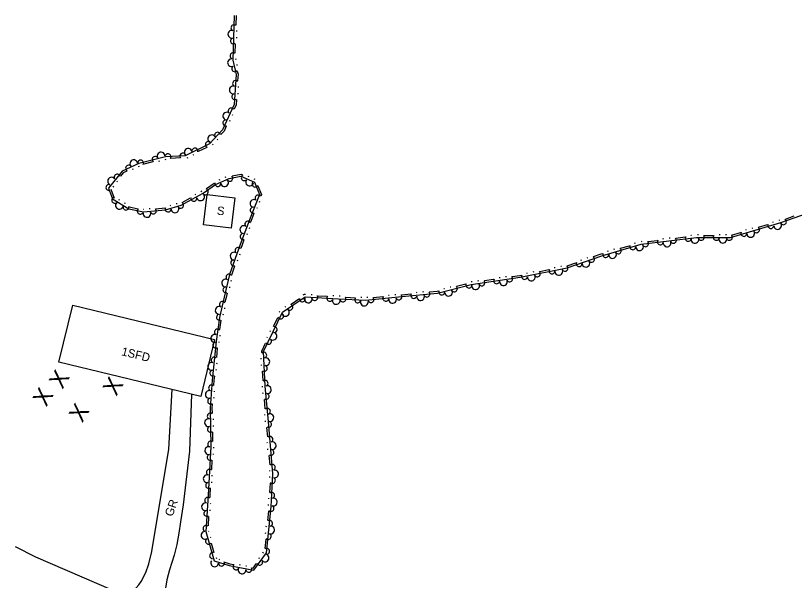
# Model space of a CAD drawing. Extents: x 2030130 to 2036320, y 723205 to 762423.
# Drawn here: x 2032703.1 to 2033043.9, y 760651.9 to 760899.1 of the extents above; entities that cross this region are included whole.
import ezdxf

# ---------------------------------------------------------------- set-up
doc = ezdxf.new("R2010")
doc.units = 0
for name, color, linetype in [('Draft_Station Labels Major', 7, 'Continuous'), ('Draft_Station Tics Major', 7, 'Continuous'), ('Exist Terrain Model Ground Surface', 7, 'Continuous'), ('Old_Level_23', 7, 'Continuous'), ('Old_Level_28', 7, 'Continuous')]:
    doc.layers.add(name, color=color, linetype=linetype)

msp = doc.modelspace()

# ---------------------------------------------------------------- linework, layer by layer
at = {"layer": 'Draft_Station Labels Major'}
for points in [[(2032752.34, 760644.62), (2032757.03, 760649.97), (2032757.96, 760651.43), (2032760.11, 760655.38), (2032761.37, 760659.07), (2032762.73, 760664.47), (2032770.18, 760709.31), (2032771.53, 760735.41)], [(2032780.04, 760733.35), (2032779.16, 760708.37), (2032776.48, 760684.96), (2032775.31, 760677.51), (2032774.46, 760672.51), (2032773.6, 760667.55), (2032772.54, 760662.87), (2032770.43, 760656.46), (2032769.22, 760652.17), (2032768.74, 760648.45), (2032768.83, 760645.51), (2032768.92, 760637.43)], [(2032711.99, 760662.1), (2032703.07, 760666.56)], [(2032832.59, 760613.36), (2032771.69, 760636.24), (2032711.99, 760662.1)]]:
    msp.add_lwpolyline(points, dxfattribs=at)
at = {"layer": 'Draft_Station Tics Major'}
for points in [[(2032798.8, 760899.06), (2032798.14, 760879.49), (2032799.59, 760873.3), (2032798.75, 760860.19), (2032793.65, 760849), (2032787.97, 760842.9), (2032777.3, 760837.65), (2032768.66, 760837.26), (2032756.95, 760834.28), (2032749.65, 760830.97), (2032743.72, 760823.56), (2032745.5, 760818.8), (2032752.65, 760814.53), (2032758.98, 760813.13), (2032768.63, 760814.05), (2032775.55, 760816.12), (2032785.15, 760821.28), (2032790.56, 760825.06), (2032796.57, 760827.79), (2032801.66, 760828.77), (2032807.58, 760826.18), (2032809.76, 760820.77), (2032805.72, 760810.4), (2032801.39, 760798.94), (2032796.75, 760785.79), (2032794.4, 760775.89), (2032792.27, 760766.86), (2032790.83, 760756.37), (2032789.08, 760739.57), (2032788.21, 760727.24), (2032788.5, 760710.53), (2032787.32, 760689.21), (2032786.31, 760673.29), (2032789.94, 760660.49), (2032796.57, 760658.39), (2032807.39, 760656.32), (2032812.88, 760663.96), (2032814.92, 760684.01), (2032815.62, 760698.69), (2032813.7, 760721.21), (2032812.31, 760736.89), (2032811.61, 760752.06), (2032819.84, 760769.24), (2032829.81, 760775.92), (2032844.36, 760775.15), (2032856.14, 760774.47), (2032872.12, 760776.08), (2032887.67, 760777.61), (2032902.42, 760781.36), (2032923.89, 760784.53), (2032944.5, 760788.67), (2032959.57, 760793.98), (2032976.86, 760798.98), (2033001.04, 760802.01), (2033015.88, 760802.01), (2033037.97, 760808.43), (2033060.92, 760816.48)], [(2032799.62, 760899.03), (2032799.48, 760894.93)], [(2032799.81, 760892.46), (2032799.79, 760892.05)], [(2032799.71, 760889.59), (2032799.7, 760889.18)], [(2032799.2, 760886.73), (2032799.07, 760882.64)], [(2032799.4, 760880.16), (2032799.38, 760879.75)], [(2032799.83, 760877.67), (2032799.92, 760877.27)], [(2032800.08, 760874.78), (2032800.41, 760873.37), (2032800.23, 760870.48)], [(2032800.3, 760865.13), (2032800.27, 760864.73)], [(2032800.48, 760868), (2032800.46, 760867.59)], [(2032799.71, 760862.3), (2032799.56, 760859.99), (2032798.69, 760858.09)], [(2032798.05, 760855.68), (2032797.88, 760855.3)], [(2032796.86, 760853.07), (2032796.69, 760852.69)], [(2032795.29, 760850.62), (2032794.34, 760848.54), (2032792.93, 760847.02)], [(2032791.55, 760844.94), (2032791.27, 760844.64)], [(2032786.71, 760841.36), (2032783.03, 760839.55)], [(2032789.59, 760842.83), (2032789.31, 760842.53)], [(2032781, 760838.1), (2032780.64, 760837.92)], [(2032763.17, 760835.02), (2032759.19, 760834)], [(2032766.05, 760835.33), (2032765.65, 760835.23)], [(2032768.83, 760836.04), (2032768.44, 760835.94)], [(2032775.12, 760836.73), (2032771.02, 760836.55)], [(2032778.42, 760836.83), (2032778.05, 760836.65)], [(2032751.73, 760831.02), (2032750.17, 760830.31), (2032748.93, 760828.76)], [(2032754.52, 760831.83), (2032754.15, 760831.66)], [(2032757.13, 760833.01), (2032756.76, 760832.84)], [(2032794.81, 760828.34), (2032795.18, 760828.51)], [(2032797.88, 760828.88), (2032801.75, 760829.62), (2032802.37, 760829.35)], [(2032804.78, 760828.74), (2032805.16, 760828.58)], [(2032807.41, 760827.59), (2032807.79, 760827.43)], [(2032745.91, 760824.34), (2032745.66, 760824.02)], [(2032747.71, 760826.58), (2032747.45, 760826.26)], [(2032786.64, 760823.32), (2032790, 760825.67)], [(2032792.19, 760827.15), (2032792.57, 760827.32)], [(2032809.14, 760824.49), (2032810.64, 760820.78), (2032810.37, 760820.08)], [(2032744.8, 760823.02), (2032746.24, 760819.18)], [(2032781.62, 760820.78), (2032781.98, 760820.97)], [(2032784.15, 760822.13), (2032784.51, 760822.33)], [(2032748.17, 760818.64), (2032748.52, 760818.43)], [(2032776.03, 760817.31), (2032779.65, 760819.25)], [(2032809.86, 760817.63), (2032809.71, 760817.25)], [(2032750.63, 760817.17), (2032750.98, 760816.96)], [(2032752.89, 760815.34), (2032752.96, 760815.3), (2032756.62, 760814.49)], [(2032759.05, 760814.37), (2032759.13, 760814.38)], [(2032761.58, 760814.61), (2032761.99, 760814.65)], [(2032764.48, 760814.47), (2032768.48, 760814.86)], [(2032770.65, 760815.93), (2032771.04, 760816.05)], [(2032773.39, 760816.75), (2032773.79, 760816.87)], [(2032808.82, 760814.96), (2032808.67, 760814.58)], [(2032807.39, 760812.43), (2032806.49, 760810.11), (2032805.92, 760808.62)], [(2033039.98, 760810), (2033043.85, 760811.36)], [(2033028.25, 760806.46), (2033032.18, 760807.6)], [(2033034.43, 760808.69), (2033034.83, 760808.8)], [(2033037.19, 760809.48), (2033037.58, 760809.6)], [(2032805.44, 760806.17), (2032805.29, 760805.79)], [(2033016.43, 760803.03), (2033020.37, 760804.17)], [(2033022.62, 760805.25), (2033023.01, 760805.37)], [(2033025.38, 760806.05), (2033025.77, 760806.17)], [(2032803.02, 760800.94), (2032802.16, 760798.66), (2032801.61, 760797.11)], [(2032804.42, 760803.48), (2032804.27, 760803.1)], [(2032976.95, 760800.23), (2032977.35, 760800.28)], [(2032979.85, 760800.18), (2032983.92, 760800.69)], [(2032986.3, 760801.4), (2032986.71, 760801.45)], [(2032989.16, 760801.76), (2032989.56, 760801.81)], [(2032992.05, 760801.71), (2032996.12, 760802.22)], [(2032998.51, 760802.93), (2032998.92, 760802.98)], [(2033001.52, 760803.24), (2033001.93, 760803.24)], [(2033004.39, 760802.83), (2033008.49, 760802.83)], [(2033010.95, 760803.24), (2033011.36, 760803.24)], [(2033013.82, 760803.24), (2033014.23, 760803.24)], [(2032964.93, 760796.81), (2032965.33, 760796.93)], [(2032967.8, 760797.21), (2032971.74, 760798.35)], [(2032973.99, 760799.43), (2032974.39, 760799.54)], [(2032801.18, 760794.66), (2032801.04, 760794.27)], [(2032956, 760793.59), (2032959.32, 760794.76), (2032959.92, 760794.94)], [(2032962.17, 760796.01), (2032962.57, 760796.13)], [(2032800.22, 760791.95), (2032800.09, 760791.56)], [(2032944.4, 760789.5), (2032948.27, 760790.87)], [(2032950.45, 760792.07), (2032950.83, 760792.21)], [(2032953.16, 760793.02), (2032953.54, 760793.16)], [(2032798.88, 760789.38), (2032797.52, 760785.51)], [(2032929.56, 760786.92), (2032929.96, 760787)], [(2032932.45, 760787.09), (2032936.47, 760787.89)], [(2032938.81, 760788.78), (2032939.21, 760788.86)], [(2032941.62, 760789.34), (2032942.02, 760789.43)], [(2032908.23, 760783.05), (2032912.29, 760783.65)], [(2032914.66, 760784.41), (2032915.07, 760784.47)], [(2032917.5, 760784.83), (2032917.91, 760784.89)], [(2032920.4, 760784.84), (2032923.75, 760785.34), (2032924.41, 760785.47)], [(2032926.74, 760786.36), (2032927.14, 760786.44)], [(2032796.72, 760780.31), (2032796.62, 760779.91)], [(2032797.38, 760783.1), (2032797.28, 760782.71)], [(2032893.22, 760780.29), (2032893.62, 760780.39)], [(2032896.1, 760780.6), (2032900.08, 760781.61)], [(2032902.49, 760782.61), (2032902.9, 760782.67)], [(2032905.33, 760783.03), (2032905.74, 760783.09)], [(2032795.65, 760777.61), (2032795.2, 760775.7), (2032794.71, 760773.62)], [(2032828.89, 760776.78), (2032829.47, 760777.17), (2032830, 760777.14)], [(2032832.45, 760777.01), (2032832.86, 760776.99)], [(2032835.3, 760776.45), (2032839.39, 760776.23)], [(2032841.87, 760776.51), (2032842.28, 760776.49)], [(2032844.75, 760776.36), (2032845.15, 760776.34)], [(2032866.22, 760776.72), (2032866.62, 760776.76)], [(2032869.07, 760777.01), (2032869.48, 760777.05)], [(2032871.97, 760776.89), (2032872.04, 760776.9), (2032876.05, 760777.29)], [(2032878.46, 760777.94), (2032878.87, 760777.98)], [(2032881.32, 760778.22), (2032881.73, 760778.26)], [(2032884.22, 760778.09), (2032887.53, 760778.42), (2032888.16, 760778.58)], [(2032890.44, 760779.58), (2032890.84, 760779.68)], [(2032823.66, 760772.79), (2032827.07, 760775.07)], [(2032847.59, 760775.78), (2032851.68, 760775.55)], [(2032854.16, 760775.81), (2032854.57, 760775.79)], [(2032856.83, 760775.77), (2032857.24, 760775.82)], [(2032859.73, 760775.65), (2032863.81, 760776.07)], [(2032794.54, 760771.13), (2032794.45, 760770.73)], [(2032818.48, 760769.24), (2032818.65, 760769.61)], [(2032821.05, 760771.53), (2032821.39, 760771.76)], [(2032793.88, 760768.34), (2032793.79, 760767.94)], [(2032816.01, 760763.14), (2032817.78, 760766.84)], [(2032792.94, 760765.7), (2032792.38, 760761.64)], [(2032814.4, 760760.73), (2032814.58, 760761.1)], [(2032792.06, 760756.29), (2032792.05, 760756.22), (2032792.02, 760755.93)], [(2032792.45, 760759.14), (2032792.4, 760758.74)], [(2032813.16, 760758.14), (2032813.34, 760758.51)], [(2032791.36, 760753.52), (2032790.93, 760749.45)], [(2032810.81, 760751.62), (2032810.78, 760752.23), (2032812.47, 760755.75)], [(2032810.53, 760748.73), (2032810.51, 760749.14)], [(2032791.09, 760746.96), (2032791.04, 760746.55)], [(2032810.66, 760745.86), (2032810.64, 760746.27)], [(2032790.79, 760744.1), (2032790.75, 760743.69)], [(2032811.37, 760739.33), (2032811.19, 760743.42)], [(2032790.08, 760741.29), (2032789.9, 760739.5), (2032789.74, 760737.23)], [(2032811.12, 760736.39), (2032811.08, 760736.8), (2032811.08, 760736.82)], [(2032789.97, 760734.75), (2032789.94, 760734.34)], [(2032811.37, 760733.53), (2032811.34, 760733.94)], [(2032789.16, 760729.05), (2032789.03, 760727.22), (2032789.07, 760725.02)], [(2032789.77, 760731.88), (2032789.74, 760731.47)], [(2032812.36, 760727.03), (2032812, 760731.11)], [(2032789.52, 760722.57), (2032789.53, 760722.16)], [(2032812.21, 760724.13), (2032812.17, 760724.54)], [(2032789.57, 760719.7), (2032789.58, 760719.29)], [(2032812.46, 760721.27), (2032812.43, 760721.68)], [(2032813.43, 760714.77), (2032813.08, 760718.86)], [(2032789.21, 760716.82), (2032789.28, 760712.72)], [(2032813.26, 760711.88), (2032813.23, 760712.29)], [(2032789.71, 760710.18), (2032789.69, 760709.77)], [(2032813.51, 760709.02), (2032813.47, 760709.43)], [(2032789.55, 760707.32), (2032789.53, 760706.91)], [(2032814.47, 760702.52), (2032814.12, 760706.6)], [(2032788.98, 760704.47), (2032788.76, 760700.38)], [(2032814.31, 760699.62), (2032814.27, 760700.03)], [(2032788.87, 760695.03), (2032788.85, 760694.62)], [(2032789.03, 760697.9), (2032789.01, 760697.49)], [(2032814.3, 760696.92), (2032814.32, 760697.33)], [(2032788.3, 760692.19), (2032788.14, 760689.16), (2032788.07, 760688.09)], [(2032814.4, 760690.34), (2032814.6, 760694.44)], [(2032813.86, 760687.5), (2032813.87, 760687.9)], [(2032788.32, 760685.6), (2032788.3, 760685.19)], [(2032813.72, 760684.63), (2032813.74, 760685.04)], [(2032788.14, 760682.74), (2032788.12, 760682.33)], [(2032813.5, 760678.12), (2032813.91, 760682.2)], [(2032787.55, 760679.9), (2032787.29, 760675.81)], [(2032812.8, 760675.31), (2032812.84, 760675.72)], [(2032787.55, 760673.43), (2032787.58, 760673.34)], [(2032788.25, 760670.97), (2032788.36, 760670.58)], [(2032812.51, 760672.45), (2032812.55, 760672.86)], [(2032788.64, 760668.1), (2032789.76, 760664.15)], [(2032812.25, 760665.88), (2032812.67, 760669.96)], [(2032811.29, 760663.85), (2032811.53, 760664.18)], [(2032790.82, 760661.9), (2032790.93, 760661.5)], [(2032791.99, 760661.13), (2032792.38, 760661.01)], [(2032809.61, 760661.52), (2032809.85, 760661.85)], [(2032794.6, 760659.88), (2032796.77, 760659.19), (2032798.47, 760658.86)], [(2032800.97, 760658.8), (2032801.37, 760658.72)], [(2032803.78, 760658.26), (2032804.19, 760658.18)], [(2032806.53, 760657.32), (2032807.03, 760657.22), (2032808.51, 760659.28)]]:
    msp.add_lwpolyline(points, dxfattribs=at)
for centre, radius, start, end in [((2032797.7, 760890.89), 1.69, 74.0505, 282.123), ((2032798.62, 760893.73), 1.3, 48.8553, 249.6518), ((2032798.43, 760887.99), 1.3, 106.5217, 307.3183), ((2032798.21, 760881.43), 1.3, 48.8553, 249.6518), ((2032797.55, 760878.4), 1.69, 89.1091, 297.1815), ((2032799.01, 760875.79), 1.3, 121.5802, 322.3768), ((2032799.33, 760869.31), 1.3, 47.1163, 247.9128), ((2032798.33, 760866.49), 1.69, 72.3115, 280.384), ((2032798.97, 760863.58), 1.3, 104.7827, 305.5793), ((2032797.44, 760857.31), 1.3, 26.2603, 227.0569), ((2032795.5, 760855.03), 1.69, 51.4556, 259.5281), ((2032795.06, 760852.08), 1.3, 83.9268, 284.7233), ((2032791.49, 760846.68), 1.3, 7.8371, 208.6336), ((2032788.93, 760845.13), 1.69, 33.0323, 241.1048), ((2032787.45, 760842.64), 1.3, 44.5989, 245.3955), ((2032766.74, 760837.62), 1.69, 0.2623, 208.3347), ((2032769.75, 760837.31), 1.3, 323.3511, 164.1476), ((2032776.31, 760837.61), 1.3, 21.0175, 221.8141), ((2032778.62, 760839.22), 1.69, 12.1277, 220.2002), ((2032781.56, 760839.75), 1.3, 346.9324, 187.729), ((2032754.79, 760834.2), 1.69, 10.3078, 218.3803), ((2032757.8, 760834.5), 1.3, 335.067, 175.8636), ((2032764.16, 760836.12), 1.3, 32.7335, 233.53), ((2032752.52, 760832.27), 1.3, 42.779, 243.5755), ((2032745.08, 760826.58), 1.69, 37.307, 245.3795), ((2032747.52, 760828.31), 1.3, 12.1118, 212.9083), ((2032796.83, 760827.84), 1.3, 209.3174, 50.114), ((2032803.16, 760828.11), 1.3, 117.1354, 317.9319), ((2032743.93, 760823.83), 1.3, 69.7782, 270.5748), ((2032791.58, 760825.52), 1.3, 165.223, 6.0196), ((2032794.54, 760825.96), 1.69, 190.4183, 38.4908), ((2032805.47, 760826.21), 1.69, 142.3306, 350.4031), ((2032807.92, 760825.32), 1.3, 130.4399, 331.2364), ((2032784.04, 760819.74), 1.69, 194.2099, 42.2824), ((2032786.1, 760821.94), 1.3, 233.3966, 74.1932), ((2032746.48, 760818.22), 1.3, 109.8851, 310.6816), ((2032748.52, 760816.04), 1.69, 135.0804, 343.1528), ((2032781.12, 760819.11), 1.3, 169.0146, 9.8112), ((2032807.35, 760816.85), 1.69, 54.68, 262.7525), ((2032809.16, 760819.23), 1.3, 29.4847, 230.2813), ((2032751.41, 760815.27), 1.3, 167.5515, 8.3481), ((2032757.64, 760813.42), 1.3, 128.2515, 329.048), ((2032763.33, 760813.54), 1.3, 203.8875, 44.684), ((2032769.82, 760814.4), 1.3, 157.4154, 358.212), ((2032772.8, 760814.44), 1.69, 182.6107, 30.6831), ((2032775.32, 760816.05), 1.3, 215.0819, 55.8784), ((2032807.08, 760813.88), 1.3, 87.1512, 287.9478), ((2032760.55, 760812.45), 1.69, 171.4163, 19.4888), ((2032802.94, 760805.36), 1.69, 55.2371, 263.3096), ((2032804.72, 760807.76), 1.3, 30.0419, 230.8384), ((2033033.59, 760807.16), 1.3, 156.9706, 357.7672), ((2033036.58, 760807.17), 1.69, 182.1659, 30.2384), ((2033039.09, 760808.82), 1.3, 217.7548, 58.5514), ((2032802.69, 760802.39), 1.3, 87.7083, 288.5049), ((2033021.78, 760803.73), 1.3, 156.9706, 357.7672), ((2033024.77, 760803.74), 1.69, 182.1659, 30.2384), ((2033027.29, 760805.33), 1.3, 214.6371, 55.4336), ((2032985.24, 760800.03), 1.3, 147.9155, 348.7121), ((2032988.19, 760799.57), 1.69, 173.1108, 21.1833), ((2032990.94, 760800.74), 1.3, 205.582, 46.3785), ((2032997.45, 760801.56), 1.3, 147.9155, 348.7121), ((2033000.4, 760801.1), 1.69, 173.1108, 21.1833), ((2033003.16, 760802.01), 1.3, 198.4444, 39.241), ((2033009.72, 760802.01), 1.3, 140.778, 341.5746), ((2033012.59, 760801.19), 1.69, 165.9733, 14.0457), ((2033015.46, 760802.01), 1.3, 198.4444, 39.241), ((2032800.43, 760796.23), 1.3, 31.3535, 232.1501), ((2032966.85, 760796.09), 1.3, 214.5511, 55.3477), ((2032973.15, 760797.91), 1.3, 156.8846, 357.6812), ((2032976.14, 760797.92), 1.69, 182.0799, 30.1524), ((2032978.73, 760799.21), 1.3, 205.582, 46.3785), ((2032798.7, 760793.79), 1.69, 56.5488, 264.6212), ((2032955.11, 760792.41), 1.3, 217.8582, 58.6548), ((2032961.33, 760794.49), 1.3, 156.8846, 357.6812), ((2032964.32, 760794.5), 1.69, 182.0799, 30.1524), ((2032798.52, 760790.81), 1.3, 89.02, 289.8165), ((2032949.7, 760790.5), 1.3, 160.1917, 0.9883), ((2032952.68, 760790.68), 1.69, 185.387, 33.4595), ((2032931.41, 760786.04), 1.3, 209.7901, 50.5866), ((2032937.84, 760787.33), 1.3, 152.1236, 352.9202), ((2032940.82, 760787.09), 1.69, 177.3189, 25.3913), ((2032943.47, 760788.46), 1.3, 209.7901, 50.5866), ((2032795, 760781.98), 1.69, 62.6415, 270.714), ((2032796.46, 760784.58), 1.3, 37.4462, 238.2428), ((2032913.63, 760783.01), 1.3, 149.165, 349.9616), ((2032916.59, 760782.62), 1.69, 174.3603, 22.4328), ((2032919.31, 760783.85), 1.3, 206.8315, 47.628), ((2032925.78, 760784.91), 1.3, 152.1236, 352.9202), ((2032928.76, 760784.67), 1.69, 177.3189, 25.3913), ((2032795.14, 760779), 1.3, 95.1127, 295.9092), ((2032895.11, 760779.5), 1.3, 212.7086, 53.5052), ((2032901.47, 760781.12), 1.3, 155.0422, 355.8387), ((2032904.41, 760780.83), 1.69, 174.3603, 22.4328), ((2032907.13, 760782.06), 1.3, 206.8315, 47.628), ((2032834.03, 760775.7), 1.3, 195.4044, 36.2009), ((2032870.83, 760775.95), 1.3, 204.2005, 44.9971), ((2032877.36, 760776.6), 1.3, 146.3737, 347.1703), ((2032880.29, 760776.06), 1.69, 171.569, 19.6415), ((2032883.07, 760777.16), 1.3, 204.0402, 44.8368), ((2032889.55, 760778.09), 1.3, 155.0422, 355.8387), ((2032892.53, 760778), 1.69, 180.2375, 28.3099), ((2032793.63, 760772.61), 1.3, 37.4581, 238.2547), ((2032828.55, 760775.07), 1.3, 174.591, 15.3876), ((2032831.12, 760775.03), 1.69, 162.9332, 11.0057), ((2032840.58, 760775.35), 1.3, 137.7379, 338.5345), ((2032843.4, 760774.38), 1.69, 162.9332, 11.0057), ((2032846.31, 760775.04), 1.3, 195.1221, 35.9186), ((2032852.86, 760774.66), 1.3, 137.4556, 338.2522), ((2032855.68, 760773.67), 1.69, 162.6509, 10.7234), ((2032858.59, 760774.72), 1.3, 204.2005, 44.9971), ((2032865.11, 760775.37), 1.3, 146.5341, 347.3306), ((2032868.05, 760774.85), 1.69, 171.7294, 19.8018), ((2032792.17, 760770.01), 1.69, 62.6534, 270.7258), ((2032821.17, 760769.14), 1.69, 199.7863, 47.8588), ((2032823.1, 760771.42), 1.3, 232.2575, 73.054), ((2032792.31, 760767.03), 1.3, 95.1246, 295.9211), ((2032819.05, 760767.6), 1.3, 205.1678, 45.9643), ((2032816.22, 760761.68), 1.3, 262.8342, 103.6308), ((2032790.2, 760757.79), 1.69, 68.1582, 276.2307), ((2032791.4, 760760.53), 1.3, 42.9629, 243.7595), ((2032815.72, 760758.74), 1.69, 230.3631, 78.4355), ((2032790.67, 760754.83), 1.3, 102.4807, 303.2773), ((2032813.74, 760756.5), 1.3, 205.1678, 45.9643), ((2032789.99, 760748.31), 1.3, 44.8142, 245.6108), ((2032811.68, 760750.42), 1.3, 291.0765, 131.873), ((2032812.63, 760747.59), 1.69, 258.6053, 106.6777), ((2032788.88, 760745.54), 1.69, 70.0095, 278.082), ((2032811.95, 760744.69), 1.3, 233.41, 74.2066), ((2032789.39, 760742.6), 1.3, 102.4807, 303.2773), ((2032812.25, 760738.13), 1.3, 291.0765, 131.873), ((2032788.83, 760736.06), 1.3, 46.7468, 247.5434), ((2032813.27, 760735.34), 1.69, 261.0477, 109.1201), ((2032787.81, 760733.25), 1.69, 71.9421, 280.0146), ((2032812.71, 760732.41), 1.3, 235.8524, 76.649), ((2032788.43, 760730.33), 1.3, 104.4133, 305.2098), ((2032813.29, 760725.88), 1.3, 293.5189, 134.3154), ((2032787.5, 760720.89), 1.69, 76.9396, 285.0121), ((2032788.27, 760723.78), 1.3, 51.7443, 252.5409), ((2032814.36, 760723.09), 1.69, 261.0477, 109.1201), ((2032788.37, 760718.04), 1.3, 109.4108, 310.2074), ((2032813.79, 760720.16), 1.3, 235.6344, 76.4309), ((2032788.48, 760711.48), 1.3, 51.7443, 252.5409), ((2032814.35, 760713.62), 1.3, 293.3008, 134.0974), ((2032815.41, 760710.83), 1.69, 260.8296, 108.9021), ((2032787.57, 760708.66), 1.69, 72.8065, 280.879), ((2032814.84, 760707.9), 1.3, 235.6344, 76.4309), ((2032788.23, 760705.74), 1.3, 105.2777, 306.0743), ((2032815.39, 760701.36), 1.3, 293.3008, 134.0974), ((2032786.89, 760696.37), 1.69, 72.8065, 280.879), ((2032787.87, 760699.19), 1.3, 47.6112, 248.4078), ((2032816.43, 760698.46), 1.69, 253.242, 101.3145), ((2032787.55, 760693.46), 1.3, 105.2777, 306.0743), ((2032815.47, 760695.63), 1.3, 228.0467, 68.8433), ((2032787.17, 760686.91), 1.3, 47.1475, 247.9441), ((2032815.16, 760689.08), 1.3, 285.7132, 126.5098), ((2032815.85, 760686.17), 1.69, 253.242, 101.3145), ((2032786.17, 760684.1), 1.69, 72.3428, 280.4152), ((2032814.85, 760683.35), 1.3, 224.9593, 65.7558), ((2032786.81, 760681.18), 1.3, 104.814, 305.6105), ((2032814.19, 760676.82), 1.3, 282.6257, 123.4223), ((2032786.4, 760674.63), 1.3, 47.1475, 247.9441), ((2032814.71, 760673.88), 1.69, 250.1546, 98.227), ((2032785.94, 760671.6), 1.69, 91.7864, 299.8589), ((2032813.61, 760671.11), 1.3, 224.9593, 65.7558), ((2032787.51, 760669.06), 1.3, 124.2576, 325.0542), ((2032789.3, 760662.75), 1.3, 66.5911, 267.3877), ((2032812.94, 760664.58), 1.3, 282.6257, 123.4223), ((2032790.2, 760659.55), 1.69, 148.3927, 356.4652), ((2032809.89, 760659.8), 1.3, 195.106, 35.9026), ((2032812.23, 760661.65), 1.69, 220.3013, 68.3738), ((2032793.18, 760659.47), 1.3, 180.8639, 21.6605), ((2032799.52, 760657.83), 1.3, 129.8991, 330.6956), ((2032802.19, 760656.48), 1.69, 155.0943, 3.1668), ((2032805.16, 760656.74), 1.3, 187.5655, 28.3621)]:
    msp.add_arc(centre, radius, start, end, dxfattribs=at)
at = {"layer": 'Exist Terrain Model Ground Surface'}
for points in [[(2032785.38, 760807.41), (2032786.94, 760820.71), (2032799.01, 760819.29), (2032797.44, 760805.99)], [(2032722.04, 760747.43), (2032728.09, 760772.35), (2032790.14, 760757.29), (2032784.09, 760732.36)]]:
    msp.add_lwpolyline(points, close=True, dxfattribs=at)

# ---------------------------------------------------------------- texts
at = {"layer": 'Draft_Station Tics Major'}
for p in [(2032723.58, 760735.27), (2032747.11, 760732.22), (2032716.47, 760727.52), (2032732.23, 760720.62)]:
    msp.add_text('X', height=7.38, rotation=58.9267, dxfattribs=at).set_placement(p)
at = {"layer": 'Old_Level_23'}
msp.add_text('GR', height=3.691, rotation=70.9971, dxfattribs=at).set_placement((2032771.74, 760679.55))
at = {"layer": 'Old_Level_28'}
for s, height, rotation, p in [('S', 3.69, 353.2823, (2032791.03, 760811.97)), ('1SFD', 3.691, 346.3536, (2032749.15, 760750.45))]:
    msp.add_text(s, height=height, rotation=rotation, dxfattribs=at).set_placement(p)

doc.saveas('drawing.dxf')
